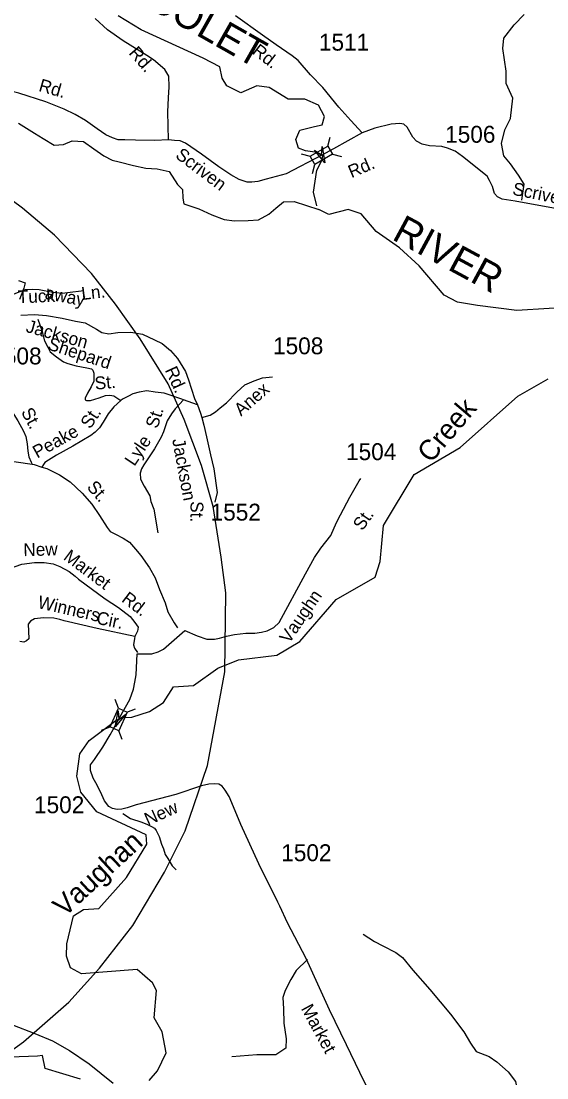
# Model space of a CAD drawing. Extents: x 990631 to 1056237, y 535999 to 585651.
# Drawn here: x 1035304 to 1039191, y 543231 to 551047 of the extents above; entities that cross this region are included whole.
import ezdxf

# ---------------------------------------------------------------- set-up
doc = ezdxf.new("R2010")
doc.units = 0
for name, color, linetype in [('Exist Boundary Political City Limit New', 7, 'Continuous'), ('Exist Hydrographic Creek Single Shore', 7, 'Continuous'), ('Exist Hydrographic Creek Single Shore Label', 7, 'Continuous'), ('Exist Hydrographic River Shore', 7, 'Continuous'), ('Exist Hydrographic River Shore Label', 7, 'Continuous'), ('Exist Railroad Mainline', 7, 'Continuous'), ('Exist Road Non-System Type 51', 7, 'Continuous'), ('Exist Road Non-System Type 51 Label', 7, 'Continuous'), ('Exist Road Secondary Structure Standard Bridge Attributed CELL', 7, 'Continuous'), ('Exist Road Secondary Structure Standard Bridge CELL', 7, 'Continuous'), ('Exist Road Secondary Type 41 Attributed', 7, 'Continuous'), ('Exist Road Secondary Type 51 Attributed', 7, 'Continuous'), ('Exist Road Secondary Type 51 Label', 7, 'Continuous'), ('Exist Road Secondary Type 51 Number Label', 7, 'Continuous')]:
    doc.layers.add(name, color=color, linetype=linetype)

msp = doc.modelspace()

# ---------------------------------------------------------------- linework, layer by layer
at = {"layer": 'Exist Boundary Political City Limit New'}
for points in [[(1035656.6, 543790.2), (1035883, 544043.1), (1036129.2, 544357.5), (1036364.1, 544752.1), (1036515.9, 545059.6), (1036681.5, 545542.6), (1036809.9, 546234.9), (1036818.6, 546818.9), (1036782.9, 547082.3), (1036724.9, 547458.4), (1036636.5, 547759.5), (1036509.6, 548101.8), (1036389.8, 548363.7), (1036184.2, 548698.6), (1036000.6, 548954.6), (1035823.7, 549180.4), (1035550.5, 549465.4), (1035314.8, 549663.1), (1035025.4, 549876.6)], [(1035321, 543498.6), (1035656.6, 543790.2)], [(1035741.9, 543221.9), (1035482.2, 543299.5), (1035462.9, 543396.4), (1035424.1, 543392.6), (1035222.6, 543384.8), (1035152.8, 543326.6), (1035035.6, 543293), (1035321, 543498.6)]]:
    msp.add_lwpolyline(points, dxfattribs=at)
at = {"layer": 'Exist Hydrographic Creek Single Shore'}
for points in [[(1035285.3, 550293.5), (1035403.4, 550218.5), (1035467.6, 550179), (1035547.7, 550130.9), (1035617.6, 550135.5), (1035681.5, 550162.2), (1035765.5, 550158.2), (1035842.5, 550101.6), (1035914.7, 550050.1), (1035976.4, 550019.6), (1036028.5, 550006.1), (1036133.7, 549980), (1036225.8, 549960.7), (1036308.7, 549954.9), (1036398.9, 549935.6), (1036459.7, 549837.8), (1036498.1, 549802), (1036500.6, 549738), (1036506.9, 549695.9), (1036617.1, 549657.9), (1036713.5, 549615.6), (1036805.8, 549580.3), (1036881.8, 549570.9), (1036981.8, 549571.7), (1037057.8, 549578.4), (1037135.4, 549620.2), (1037186.6, 549662.9), (1037242.7, 549711), (1037321.6, 549713.9), (1037505.9, 549653.8)], [(1036250.7, 543212.8), (1036312, 543284), (1036375.5, 543417.6), (1036347, 543571.3), (1036287.7, 543674.8), (1036304.4, 543877.6), (1036274.5, 543934.6), (1036160.8, 544032.1), (1035751.3, 544001), (1035669.3, 544045.3), (1035638.7, 544131.2), (1035641.8, 544223.1), (1035689.9, 544429.7), (1035765.2, 544475.7), (1035878, 544484), (1036082.9, 544714), (1036232.2, 544960.2), (1036229.2, 545029.8), (1035864.7, 545199.9), (1035744.3, 545343.4), (1035714.8, 545462.2), (1035736.7, 545629.1), (1035806.8, 545726.2), (1036004.6, 545873.3), (1036049.6, 545896.4), (1036122.7, 545899.4), (1036251.7, 545941.4), (1036356.8, 546008.5), (1036429.9, 546122.7), (1036578.5, 546134), (1036757.7, 546261.6), (1036909.9, 546324.2), (1037194.4, 546357.8), (1037364.4, 546459.5), (1037632.8, 546769.1), (1037921.8, 546934), (1037958.8, 547051.4), (1037983.9, 547316.7), (1038209.7, 547694.2), (1038549.6, 547894.2), (1038976.7, 548274.3), (1039200.8, 548402.5)]]:
    msp.add_lwpolyline(points, dxfattribs=at)
at = {"layer": 'Exist Hydrographic River Shore'}
for points in [[(1037489.9, 549681.9), (1037465.9, 549782), (1037489.9, 549944.2), (1037529.9, 550020.3), (1037533.9, 550052.4), (1037493.9, 550076.4), (1037405.8, 550088.4), (1037353.8, 550108.5), (1037333.8, 550172.6), (1037365.8, 550240.7), (1037473.9, 550268.7), (1037529.9, 550280.7), (1037545.9, 550340.8), (1037501.9, 550424.9), (1037401.8, 550469), (1037277.7, 550469), (1037137.6, 550557.1), (1037045.6, 550569.1), (1036929.5, 550517), (1036825.4, 550569.1), (1036789.4, 550625.2), (1036773.4, 550709.3), (1036649.3, 550773.4), (1036192.2, 550982.6), (1036020.9, 551085.9)], [(1039620.2, 548931.3), (1039446.9, 548936.5), (1038968.7, 548907.2), (1038678.4, 548943.7), (1038530.6, 548968.8), (1038432.3, 549019.4), (1038246.4, 549237.2), (1038102.3, 549369.4), (1037928, 549492), (1037818.1, 549621.8), (1037722, 549653.8), (1037577.9, 549617.8), (1037505.9, 549653.8)]]:
    msp.add_lwpolyline(points, dxfattribs=at)
at = {"layer": 'Exist Railroad Mainline'}
msp.add_lwpolyline([(1035239.2, 543623.3), (1035406.2, 543559.6), (1035536.8, 543505), (1035660.6, 543432.9), (1035807.8, 543334.8), (1035983.3, 543192.6)], dxfattribs=at)
at = {"layer": 'Exist Road Non-System Type 51'}
msp.add_line((1036607, 548208.7), (1036504.1, 548246), dxfattribs=at)
for points in [[(1039006.9, 549724), (1039023.6, 549841.1), (1038981.8, 549908), (1038923.3, 549991.7), (1038873.2, 550050.2), (1038856.4, 550142.2), (1038881.5, 550242.6), (1038923.3, 550326.2), (1038940, 550476.8), (1038889.9, 550585.5), (1038889.9, 550677.5), (1038864.8, 550844.8), (1038873.2, 550920.1), (1038948.4, 551020.4), (1039023.6, 551095.7)], [(1035767.5, 549052.3), (1035646.9, 549038.1), (1035606.8, 549033.3), (1035538.9, 549039.5), (1035437.5, 549058.7), (1035389.5, 549062.3), (1035333.5, 549060), (1035295, 549045.4), (1035211.9, 549014.1)], [(1035426.5, 548842.9), (1035455.8, 548758.1), (1035475.3, 548683.2), (1035500, 548636.5), (1035518.9, 548601.9), (1035565.8, 548564.4), (1035616.4, 548526.7), (1035650.2, 548515.7), (1035711.7, 548497.6), (1035789.2, 548483.1), (1035825.1, 548475.9), (1035834.7, 548465.7), (1035842, 548443.4), (1035842.1, 548385.4), (1035820.8, 548342), (1035795.2, 548294.9), (1035776.1, 548257.4), (1035777.6, 548245.4), (1035787.5, 548241), (1035815.6, 548242), (1035880.1, 548260.1), (1035926.7, 548278.6), (1035958.8, 548281.6), (1035988.7, 548276.6), (1036041.6, 548240.9)], [(1036504.1, 548246), (1036492.2, 548252.4), (1036361.6, 548294.7), (1036295.7, 548302.8), (1036232.1, 548312.9), (1036177.7, 548302.6), (1036129.2, 548290.1), (1036098.7, 548272.9), (1036054, 548250.4), (1036041.6, 548240.9)], [(1035198.3, 548217.9), (1035200.2, 548215.8), (1035280.3, 548091.2), (1035321.8, 548013.7), (1035338.6, 547975.1), (1035348.9, 547920.9), (1035353.2, 547866.6), (1035361.8, 547824.4), (1035378.6, 547785.9), (1035386.1, 547771.5)], [(1036041.6, 548240.9), (1035988.1, 548194.5), (1035948.4, 548143.7), (1035910.3, 548080.9), (1035883.1, 548039.8), (1035850, 548006.9), (1035819.1, 547981.9), (1035686.5, 547904.1), (1035566.3, 547837.7), (1035505.1, 547799.7), (1035478.6, 547782.7), (1035468.1, 547768.9), (1035457.5, 547749.3)], [(1036504.1, 548246), (1036443.9, 548180), (1036416.8, 548142.7), (1036383.1, 548089.8), (1036356.4, 548008.7), (1036339.1, 547971.2), (1036290.3, 547884.5), (1036210.5, 547765.1), (1036193.5, 547735.6), (1036184.4, 547704), (1036187.2, 547659.7), (1036213.5, 547607), (1036255.1, 547535.5), (1036261.8, 547493.4), (1036285.9, 547436.5), (1036314.4, 547263.4)], [(1033262.4, 547323.3), (1033348.4, 547322.6), (1033584.2, 547311), (1033712.2, 547304.8), (1033784.2, 547306.6), (1033832.8, 547327), (1033916, 547362.4), (1034146.5, 547495.2), (1034283.2, 547576.8), (1034421.4, 547644.3), (1034519.1, 547695.3), (1034622.6, 547736.1), (1034804.7, 547798.2), (1034903.1, 547809), (1035025.2, 547809.2), (1035266.6, 547787.3), (1035386.1, 547771.5)], [(1035386.1, 547771.5), (1035400, 547767), (1035457.5, 547749.3)], [(1035457.5, 547749.3), (1035493.1, 547738.1), (1035587.8, 547691), (1035666.2, 547640.4), (1035755.5, 547555.6), (1035826.9, 547475.1), (1035882.2, 547391.4), (1035939.4, 547301.4), (1035962.5, 547272.7), (1036001.9, 547251.5), (1036058.9, 547223.6), (1036104.1, 547194), (1036150.5, 547142.7), (1036189, 547095.3), (1036252.1, 547003.2), (1036293.7, 546929.9), (1036326.9, 546842.8), (1036369.8, 546745.3), (1036389.7, 546678.7), (1036435.2, 546597.2), (1036461.2, 546559.7)], [(1035184.9, 546987.5), (1035203.2, 546994.9), (1035308.4, 547029.6), (1035402.9, 547042.5), (1035472.9, 547044.3), (1035540.5, 547034.1), (1035590, 547014.5), (1035658.8, 546976.3), (1035703.7, 546942.8), (1035729.1, 546919.9), (1035924.4, 546773.7), (1036022.6, 546710.5), (1036110.5, 546643.5), (1036145, 546600.4), (1036167.9, 546563.7), (1036163.1, 546535.8), (1036145.7, 546496.3)], [(1036145.7, 546496.3), (1035865.4, 546555.4), (1035621, 546611.2), (1035589.4, 546622.2), (1035545.6, 546631.7), (1035469.6, 546634), (1035401.5, 546626.2), (1035372.9, 546609.1), (1035356.1, 546587.7), (1035358.4, 546535.6), (1035360.7, 546479.5), (1035344.2, 546464.1), (1035324, 546454.7), (1035294, 546457.7)], [(1036145.7, 546496.3), (1036143.2, 546481.2), (1036135.2, 546433.1), (1036143.2, 546409.1), (1036163.2, 546377.1)], [(1036055.7, 545186.3), (1036112.6, 545150.5), (1036195.6, 545121.8), (1036237.1, 545106.4), (1036268.8, 545091.4), (1036290.4, 545078.7), (1036301.8, 545060.3), (1036324.4, 545017.6), (1036342.6, 544959), (1036355.5, 544924.5), (1036368.1, 544884.1), (1036387.3, 544853.5), (1036421.6, 544800.4), (1036450.6, 544769.4)], [(1037832.3, 544294.8), (1037916.6, 544240.1), (1037977.6, 544208), (1038074.1, 544158.9), (1038122.9, 544121.3), (1038199.9, 544028.9), (1038325.4, 543884.7), (1038477.6, 543701.8), (1038577.6, 543572.3), (1038626, 543488.3), (1038667.8, 543425.6), (1038763.8, 543388.3), (1038822.5, 543350.3), (1038906.1, 543275.1), (1038960.5, 543204), (1038973, 543128.7), (1038977.6, 543069.3), (1038987.4, 543000.9), (1039011.3, 542934.2), (1039041, 542868.3)], [(1037422, 544105.8), (1037337.3, 544026.5), (1037297.2, 543959.6), (1037256.5, 543877), (1037238.9, 543825.6), (1037244.2, 543741.2), (1037246.6, 543635.1), (1037263.1, 543520.6), (1037260.7, 543450.6), (1037188.1, 543400.5), (1037045.9, 543400.5), (1036862, 543388)]]:
    msp.add_lwpolyline(points, dxfattribs=at)
at = {"layer": 'Exist Road Secondary Structure Standard Bridge Attributed CELL'}
for points in [[(1037530.1, 550119.8), (1037550.2, 549999.5), (1037472.7, 550093.6), (1037524.9, 550055)], [(1036077.9, 545920.8), (1036000.2, 545826.9), (1036020.6, 545947.1), (1036025.6, 545882.3)]]:
    msp.add_lwpolyline(points, close=True, dxfattribs=at)
at = {"layer": 'Exist Road Secondary Structure Standard Bridge CELL'}
for p, q in [((1037571.7, 550123.3), (1037589.6, 550189.9)), ((1037374.1, 550065.9), (1037440.7, 550048)), ((1037606.2, 550063.5), (1037672.9, 550045.7)), ((1037458.2, 549920.3), (1037476, 549986.9)), ((1036023.1, 545965.1), (1035998.3, 546029.5)), ((1036086.2, 545937.2), (1036150.6, 545962)), ((1035897.3, 545802.2), (1035961.7, 545827.1)), ((1036051.1, 545734.2), (1036026.2, 545798.5))]:
    msp.add_line(p, q, dxfattribs=at)
for points in [[(1037440.7, 550048), (1037571.6, 550123.6), (1037606.9, 550062.5), (1037476, 549986.9)], [(1035961.7, 545827.1), (1036022.8, 545965.3), (1036087.4, 545936.7), (1036026.2, 545798.5)]]:
    msp.add_lwpolyline(points, close=True, dxfattribs=at)
at = {"layer": 'Exist Road Secondary Type 41 Attributed'}
for points in [[(1036394.4, 550169.1), (1036388.4, 550377.3), (1036393.7, 550480.5), (1036398.4, 550560.5), (1036396, 550640.5), (1036365.4, 550689.9), (1036283.1, 550760.5), (1036233.7, 550794.3), (1036180.5, 550826.2), (1036059, 550902.1), (1035943.4, 550983.9), (1035852.1, 551066.9)], [(1039322.4, 549649.8), (1038957, 549716.3), (1038861.9, 549731.4), (1038825.6, 549748), (1038804.6, 549773.4), (1038789.4, 549825.1), (1038768.3, 549868.9), (1038750.1, 549900.6), (1038567.4, 550045.7), (1038513.1, 550084.9), (1038457.2, 550107.6), (1038413.4, 550119.7), (1038324.3, 550124.2), (1038270, 550137.8), (1038226.2, 550160.5), (1038199, 550189.2), (1038158.2, 550263.2), (1038134.1, 550284.4), (1038103.9, 550290.4), (1038040.5, 550285.9), (1037918.2, 550255.7), (1037825.9, 550221.6)]]:
    msp.add_lwpolyline(points, dxfattribs=at)
at = {"layer": 'Exist Road Secondary Type 51 Attributed'}
for points in [[(1037825.9, 550221.6), (1037741.2, 550311.3), (1037653.8, 550410.9), (1037534, 550555.3), (1037444.6, 550650.8), (1037353.1, 550756.5), (1037308.4, 550791.1), (1037190.6, 550872.4), (1037089, 550943.6), (1036889.9, 551085.9)], [(1036394.4, 550169.1), (1036292.5, 550165.2), (1036149.1, 550167.5), (1036071.5, 550169.9), (1036022.1, 550169.9), (1035979.8, 550184), (1035930.4, 550207.5), (1035866.9, 550249.9), (1035779.9, 550313.4), (1035702.3, 550355.8), (1035622.3, 550395.8), (1035485.9, 550449.9), (1035286, 550513.4), (1035008.5, 550584), (1034716.9, 550659.3), (1034575.8, 550694.6), (1034484.1, 550701.7), (1034391.4, 550699.5), (1034324.2, 550664), (1034263, 550631.1), (1034183.1, 550584), (1034104.9, 550551.8)], [(1037825.9, 550221.6), (1037613.2, 550101.9), (1037526.7, 550056.6)], [(1037526.7, 550056.6), (1037263.7, 549918.9), (1037115.4, 549878.2), (1037054.4, 549862), (1037009.7, 549855.9), (1036975.2, 549855.9), (1036916.3, 549876.2), (1036855.3, 549910.8), (1036765.9, 549969.7), (1036637.9, 550063.2), (1036518, 550144.6), (1036479.4, 550162.9), (1036436.7, 550164.9), (1036394.4, 550169.1)], [(1035284.7, 549128), (1035333.4, 549111.7), (1035323.3, 549071.1), (1035292.8, 548987.7)], [(1035300.9, 548871.8), (1035402.5, 548877.9), (1035491.9, 548869.8), (1035607.7, 548849.5), (1035705.3, 548827.1), (1035776.4, 548814.9), (1035861.7, 548768.2), (1035900.3, 548743.8), (1035953.2, 548735.6), (1036018.2, 548743.8), (1036115.7, 548747.8), (1036201, 548731.6), (1036290.4, 548690.9), (1036347.3, 548662.4), (1036408.3, 548611.6), (1036459.1, 548552.6), (1036518, 548455.1), (1036542.4, 548394.1), (1036586.5, 548257.3), (1036607, 548208.7), (1036630.9, 548148), (1036640.5, 548115)], [(1036640.5, 548115), (1036701.6, 548134.1), (1036740.3, 548156.9), (1036775.3, 548187.8), (1036822.5, 548224.3), (1036899.1, 548304), (1036958.8, 548356), (1037025.9, 548387.8), (1037088.7, 548408), (1037162.9, 548415.5)], [(1036640.5, 548115), (1036654.2, 548059.1), (1036675.4, 547972.4), (1036705.1, 547839.4), (1036729.3, 547735.3), (1036753.7, 547560.5), (1036735.4, 547489.3)], [(1036162.8, 546367.7), (1036216.5, 546366.5), (1036270.3, 546367.7), (1036316.7, 546383.6), (1036355.8, 546403.1), (1036415.6, 546453.2), (1036513.3, 546541.2), (1036606.1, 546499.6), (1036676.9, 546475.2), (1036734.3, 546475.2), (1036770.9, 546482.5), (1036823.4, 546498.4), (1036880.8, 546509.4), (1036966.3, 546521.6), (1037031, 546521.6), (1037081.9, 546527.6), (1037122.6, 546538.7), (1037172.7, 546562), (1037211.8, 546599.8), (1037407.1, 546960.3), (1037473.1, 547080), (1037519.5, 547149.7), (1037592.7, 547243.7), (1037635.5, 547337.8), (1037666, 547396.5), (1037733.2, 547526), (1037804, 547647), (1037815.4, 547664.3)], [(1036034.4, 545898.9), (1036106.6, 546029.2), (1036134.7, 546106.2), (1036144.5, 546157.5), (1036153.1, 546212.5), (1036162.8, 546367.7)], [(1037860.2, 543165.2), (1037807.7, 543270.3), (1037710, 543476.7), (1037584.2, 543734.6), (1037410.8, 544114.6), (1037274.6, 544378.6), (1037216.5, 544500.7), (1037201.5, 544531.2), (1037061.6, 544813.5), (1036927.5, 545104.3), (1036874.7, 545236.2), (1036841.8, 545313.2), (1036812.5, 545358.4), (1036789.3, 545389), (1036764.8, 545403.6), (1036730.6, 545406.1), (1036692.8, 545402.4), (1036637.8, 545390.2), (1036447.3, 545327.9), (1036153.1, 545250.9), (1036088.3, 545228.9), (1036049.3, 545219.1), (1036012.6, 545216.7), (1035978.4, 545222.8), (1035951.6, 545237.5), (1035921, 545280.2), (1035901.5, 545324.2), (1035864.9, 545395.1), (1035835.6, 545448.8), (1035816, 545503.8), (1035817, 545546.2), (1035846.5, 545587.2), (1035907.3, 545677.4), (1035962.4, 545767.8), (1035983.6, 545807.2), (1036034.4, 545898.9)]]:
    msp.add_lwpolyline(points, dxfattribs=at)

# ---------------------------------------------------------------- texts
at = {"layer": 'Exist Hydrographic Creek Single Shore Label'}
for s, rotation, p in [('Creek', 49.54898, (1038333.1, 547771.5)), ('Vaughan', 42.68969, (1035624.5, 544416))]:
    msp.add_text(s, height=150, rotation=rotation, dxfattribs=at).set_placement(p)
at = {"layer": 'Exist Hydrographic River Shore Label'}
for s, rotation, p in [('PACOLET', 330.43346, (1035896.4, 551342.1)), ('RIVER', 331.62179, (1038037.7, 549436.7))]:
    msp.add_text(s, height=210, rotation=rotation, dxfattribs=at).set_placement(p)
at = {"layer": 'Exist Road Non-System Type 51 Label'}
for s, rotation, p in [('Ln.', 6.70954, (1035754.7, 548984.2)), ('Tuck', 2.3206, (1035280.8, 548960)), ('away', 349.25596, (1035474.6, 548993.7)), ('Shepard', 341.83795, (1035493.8, 548621.2)), ('St.', 5.26616, (1035851.9, 548321.1)), ('St.', 298.15338, (1035300.7, 548157.4)), ('St.', 56.44615, (1035814.7, 548025.7)), ('St.', 71.81228, (1036311.2, 548028.6)), ('Peake', 28.92293, (1035422.3, 547810.9)), ('Lyle', 56.24053, (1036141.1, 547749.8)), ('St.', 311.58446, (1035784.4, 547597.2)), ('New', 1.46332, (1035321.1, 547089.6)), ('Market', 323.18754, (1035610, 547070.5)), ('Rd.', 322.68067, (1036040, 546759.1)), ('Winners', 347.15043, (1035420.9, 546707.3)), ('Cir.', 348.10093, (1035854.8, 546591.2))]:
    msp.add_text(s, height=95, rotation=rotation, dxfattribs=at).set_placement(p)
at = {"layer": 'Exist Road Secondary Type 51 Label'}
for s, rotation, p in [('Rd.', 322.25201, (1037005.5, 550811.6)), ('Rd.', 311.25955, (1036094.8, 550808.8)), ('Rd.', 343.89616, (1035427.8, 550532)), ('Scriven', 323.0438, (1036437.8, 550042.1)), ('Rd.', 23.02641, (1037746.5, 549885.1)), ('Scriven', 348.70958, (1038931.9, 549763.7)), ('Jackson', 344.39677, (1035333, 548749.7)), ('Rd.', 294.3553, (1036365.2, 548467.2)), ('Anex', 41.0816, (1036929.7, 548121.1)), ('Jackson', 280.54976, (1036420.2, 547951.8)), ('St.', 269.5442, (1036556.7, 547496.9)), ('St.', 54.89712, (1037827.6, 547272.6)), ('Vaughn', 55.56885, (1037285.4, 546437.7)), ('New', 23.90844, (1036240.9, 545095.6)), ('Market', 298.44851, (1037370.4, 543744.6))]:
    msp.add_text(s, height=95, rotation=rotation, dxfattribs=at).set_placement(p)
at = {"layer": 'Exist Road Secondary Type 51 Number Label'}
for s, p in [('1511', (1037505.8, 550829.1)), ('1506', (1038439.1, 550147.7)), ('1508', (1037166.5, 548583.3)), ('1508', (1035083.3, 548508.3)), ('1504', (1037706.3, 547800.3)), ('1552', (1036704.8, 547353)), ('1502', (1035399, 545188.7)), ('1502', (1037226.9, 544834))]:
    msp.add_text(s, height=125, dxfattribs=at).set_placement(p)

doc.saveas('drawing.dxf')
